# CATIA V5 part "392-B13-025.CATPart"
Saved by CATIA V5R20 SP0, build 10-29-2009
Part number: 392-B13-025
Definition: NONE
Nomenclature: 392-B13-025
Source: Unknown
Description: 392-B13-025
Bounding box of the stored display mesh (mm): x 0 to 25, y -6.146 to 6.146, z -6.1 to 5.947
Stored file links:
  C:\Users\Utente\Desktop\IO LAVORO\3D X SITO CF\X SITO\3D files 392B\392-B13-025.CATPart
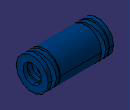
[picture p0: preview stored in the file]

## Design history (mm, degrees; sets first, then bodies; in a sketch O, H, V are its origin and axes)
Body1 "392-B13-025" (main body)
  Solid1: solid without history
